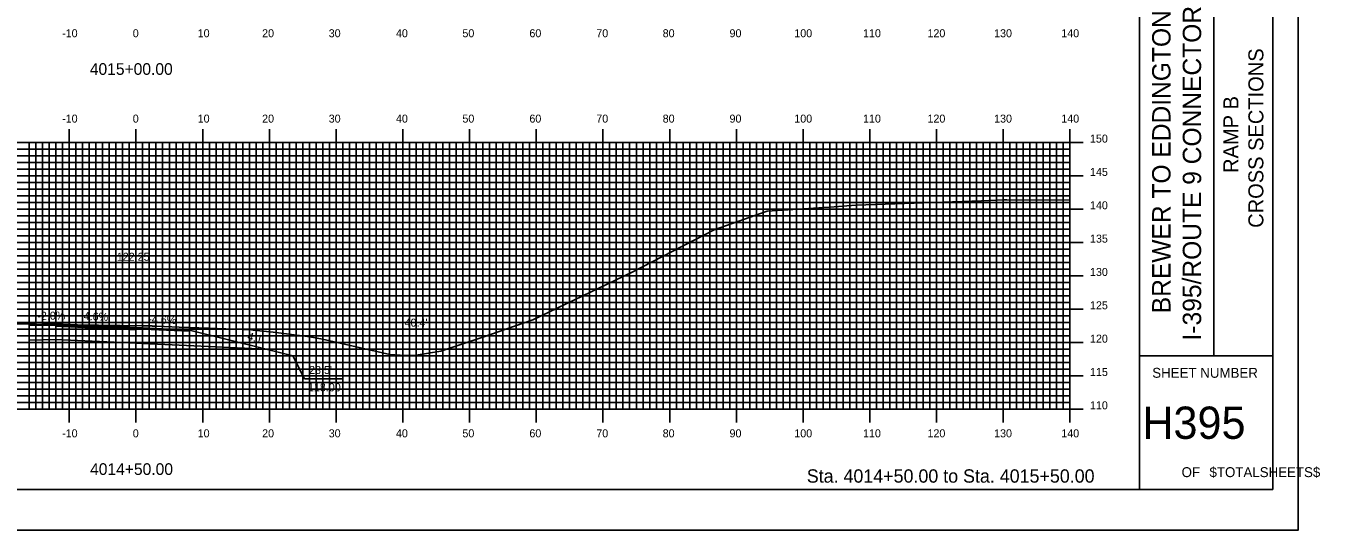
# Model space of a CAD drawing. Extents: x 853721 to 854064, y 364661 to 364881.
# Drawn here: x 853870.3 to 854064.3, y 364661.3 to 364736.9 of the extents above; entities that cross this region are included whole.
import ezdxf

# ---------------------------------------------------------------- set-up
doc = ezdxf.new("R2010")
doc.units = 0
for name, color, linetype in [('ANNOTATION', 7, 'Continuous'), ('BORDER', 7, 'Continuous'), ('D_Roadway_Centerline_Text', 7, 'Continuous'), ('D_Roadway_Edge_Shoulder', 7, 'Continuous'), ('D_Roadway_Edge_TW', 7, 'Continuous'), ('D_Roadway_Pavement', 7, 'Continuous'), ('D_Roadway_SubGrade', 7, 'Continuous'), ('D_Text_Standard', 7, 'Continuous'), ('H_V ANNOTATION', 7, 'Continuous'), ('M_Roadway_Centerline', 7, 'Continuous'), ('MAJOR', 7, 'Continuous'), ('MINOR', 7, 'Continuous'), ('PLOT BOUNDARY', 7, 'Continuous'), ('S_Roadway_Centerline', 7, 'Continuous')]:
    doc.layers.add(name, color=color, linetype=linetype)

msp = doc.modelspace()

# ---------------------------------------------------------------- linework, layer by layer
at = {"layer": 'ANNOTATION'}
for points in [[(853906.3, 364688.38), (853910.3, 364687.38), (853927.16, 364687.44)], [(853917.76, 364683.95), (853912.07, 364683.95), (853910.3, 364687.38)]]:
    msp.add_lwpolyline(points, dxfattribs=at)
at = {"layer": 'BORDER'}
for p, q in [((854037.21, 364667.37), (854037.21, 364877.37)), ((854048.39, 364687.38), (854048.39, 364757.38)), ((854037.21, 364687.38), (854057.21, 364687.38))]:
    msp.add_line(p, q, dxfattribs=at)
msp.add_lwpolyline([(853737.21, 364667.37), (854057.21, 364667.37), (854057.21, 364877.37), (853737.21, 364877.37)], close=True, dxfattribs=at)
at = {"layer": 'D_Roadway_Edge_Shoulder'}
for points in [[(853874.81, 364692.17), (853870.81, 364692.09), (853870.81, 364691.92), (853874.81, 364691.99)], [(853886.81, 364691.62), (853894.81, 364691.25), (853894.81, 364691.08), (853886.81, 364691.44)]]:
    msp.add_lwpolyline(points, close=True, dxfattribs=at)
at = {"layer": 'D_Roadway_Edge_TW'}
msp.add_lwpolyline([(853874.81, 364692.17), (853886.81, 364691.62), (853886.81, 364691.44), (853874.81, 364691.99)], close=True, dxfattribs=at)
at = {"layer": 'D_Roadway_Pavement'}
msp.add_lwpolyline([(853874.81, 364691.99), (853886.81, 364691.44), (853886.81, 364691.27), (853874.81, 364691.82)], close=True, dxfattribs=at)
for points in [[(853874.81, 364691.99), (853874.81, 364691.82)], [(853886.81, 364691.44), (853886.81, 364691.27)], [(853886.81, 364691.44), (853886.81, 364691.27)]]:
    msp.add_lwpolyline(points, dxfattribs=at)
at = {"layer": 'D_Roadway_SubGrade'}
msp.add_line((853870.81, 364699.37), (853870.81, 364689.74), dxfattribs=at)
for points in [[(853874.81, 364689.82), (853870.81, 364689.74), (853870.81, 364692.09), (853870.81, 364691.92), (853874.81, 364691.99), (853874.81, 364691.82)], [(853874.81, 364691.82), (853886.81, 364691.27), (853886.81, 364689.27), (853874.81, 364689.82)], [(853886.81, 364691.27), (853886.81, 364691.44), (853894.81, 364691.08), (853894.81, 364691.25), (853906.3, 364688.38), (853886.81, 364689.27)]]:
    msp.add_lwpolyline(points, close=True, dxfattribs=at)
at = {"layer": 'MAJOR'}
for p, q in [((853876.81, 364721.37), (853876.81, 364719.37)), ((853886.81, 364721.37), (853886.81, 364719.37)), ((853896.81, 364721.37), (853896.81, 364719.37)), ((853906.81, 364721.37), (853906.81, 364719.37)), ((853916.81, 364721.37), (853916.81, 364719.37)), ((853926.81, 364721.37), (853926.81, 364719.37)), ((853936.81, 364721.37), (853936.81, 364719.37)), ((853946.81, 364721.37), (853946.81, 364719.37)), ((853956.81, 364721.37), (853956.81, 364719.37)), ((853966.81, 364721.37), (853966.81, 364719.37)), ((853976.81, 364721.37), (853976.81, 364719.37)), ((853986.81, 364721.37), (853986.81, 364719.37)), ((853996.81, 364721.37), (853996.81, 364719.37)), ((854006.81, 364721.37), (854006.81, 364719.37)), ((854016.81, 364721.37), (854016.81, 364719.37)), ((854026.81, 364721.37), (854026.81, 364719.37)), ((853746.81, 364719.37), (854026.81, 364719.37)), ((853746.81, 364719.37), (854026.81, 364719.37)), ((853876.81, 364679.37), (853876.81, 364719.37)), ((853886.81, 364679.37), (853886.81, 364719.37)), ((853896.81, 364679.37), (853896.81, 364719.37)), ((853906.81, 364679.37), (853906.81, 364719.37)), ((853916.81, 364679.37), (853916.81, 364719.37)), ((853926.81, 364679.37), (853926.81, 364719.37)), ((853936.81, 364679.37), (853936.81, 364719.37)), ((853946.81, 364679.37), (853946.81, 364719.37)), ((853956.81, 364679.37), (853956.81, 364719.37)), ((853966.81, 364679.37), (853966.81, 364719.37)), ((853976.81, 364679.37), (853976.81, 364719.37)), ((853986.81, 364679.37), (853986.81, 364719.37)), ((853996.81, 364679.37), (853996.81, 364719.37)), ((854006.81, 364679.37), (854006.81, 364719.37)), ((854016.81, 364679.37), (854016.81, 364719.37)), ((854028.81, 364719.37), (854024.8, 364719.37)), ((854026.81, 364679.37), (854026.81, 364719.37)), ((854026.81, 364679.37), (854026.81, 364719.37)), ((853746.81, 364714.37), (854026.81, 364714.37)), ((854028.81, 364714.37), (854024.8, 364714.37)), ((853746.81, 364709.37), (854026.81, 364709.37)), ((854028.81, 364709.37), (854024.8, 364709.37)), ((853746.81, 364704.37), (854026.81, 364704.37)), ((854028.81, 364704.37), (854024.8, 364704.37)), ((853746.81, 364699.37), (854026.81, 364699.37)), ((854028.81, 364699.37), (854024.8, 364699.37)), ((853746.81, 364694.37), (854026.81, 364694.37)), ((854028.81, 364694.37), (854024.8, 364694.37)), ((853746.81, 364689.37), (854026.81, 364689.37)), ((854028.81, 364689.37), (854024.8, 364689.37)), ((853746.81, 364684.37), (854026.81, 364684.37)), ((854028.81, 364684.37), (854024.8, 364684.37)), ((853746.81, 364679.37), (854026.81, 364679.37)), ((853746.81, 364679.37), (854026.81, 364679.37)), ((853876.81, 364677.37), (853876.81, 364679.37)), ((853886.81, 364677.37), (853886.81, 364679.37)), ((853896.81, 364677.37), (853896.81, 364679.37)), ((853906.81, 364677.37), (853906.81, 364679.37)), ((853916.81, 364677.37), (853916.81, 364679.37)), ((853926.81, 364677.37), (853926.81, 364679.37)), ((853936.81, 364677.37), (853936.81, 364679.37)), ((853946.81, 364677.37), (853946.81, 364679.37)), ((853956.81, 364677.37), (853956.81, 364679.37)), ((853966.81, 364677.37), (853966.81, 364679.37)), ((853976.81, 364677.37), (853976.81, 364679.37)), ((853986.81, 364677.37), (853986.81, 364679.37)), ((853996.81, 364677.37), (853996.81, 364679.37)), ((854006.81, 364677.37), (854006.81, 364679.37)), ((854016.81, 364677.37), (854016.81, 364679.37)), ((854028.81, 364679.37), (854024.8, 364679.37)), ((854026.81, 364677.37), (854026.81, 364679.37))]:
    msp.add_line(p, q, dxfattribs=at)
at = {"layer": 'MINOR'}
for p, q in [((853870.81, 364679.37), (853870.81, 364719.37)), ((853871.81, 364679.37), (853871.81, 364719.37)), ((853872.81, 364679.37), (853872.81, 364719.37)), ((853873.81, 364679.37), (853873.81, 364719.37)), ((853874.81, 364679.37), (853874.81, 364719.37)), ((853875.81, 364679.37), (853875.81, 364719.37)), ((853877.81, 364679.37), (853877.81, 364719.37)), ((853878.81, 364679.37), (853878.81, 364719.37)), ((853879.81, 364679.37), (853879.81, 364719.37)), ((853880.81, 364679.37), (853880.81, 364719.37)), ((853881.81, 364679.37), (853881.81, 364719.37)), ((853882.81, 364679.37), (853882.81, 364719.37)), ((853883.81, 364679.37), (853883.81, 364719.37)), ((853884.81, 364679.37), (853884.81, 364719.37)), ((853885.81, 364679.37), (853885.81, 364719.37)), ((853887.81, 364679.37), (853887.81, 364719.37)), ((853888.81, 364679.37), (853888.81, 364719.37)), ((853889.81, 364679.37), (853889.81, 364719.37)), ((853890.81, 364679.37), (853890.81, 364719.37)), ((853891.81, 364679.37), (853891.81, 364719.37)), ((853892.81, 364679.37), (853892.81, 364719.37)), ((853893.81, 364679.37), (853893.81, 364719.37)), ((853894.81, 364679.37), (853894.81, 364719.37)), ((853895.81, 364679.37), (853895.81, 364719.37)), ((853897.81, 364679.37), (853897.81, 364719.37)), ((853898.81, 364679.37), (853898.81, 364719.37)), ((853899.81, 364679.37), (853899.81, 364719.37)), ((853900.81, 364679.37), (853900.81, 364719.37)), ((853901.81, 364679.37), (853901.81, 364719.37)), ((853902.81, 364679.37), (853902.81, 364719.37)), ((853903.81, 364679.37), (853903.81, 364719.37)), ((853904.81, 364679.37), (853904.81, 364719.37)), ((853905.81, 364679.37), (853905.81, 364719.37)), ((853907.81, 364679.37), (853907.81, 364719.37)), ((853908.81, 364679.37), (853908.81, 364719.37)), ((853909.81, 364679.37), (853909.81, 364719.37)), ((853910.81, 364679.37), (853910.81, 364719.37)), ((853911.81, 364679.37), (853911.81, 364719.37)), ((853912.81, 364679.37), (853912.81, 364719.37)), ((853913.81, 364679.37), (853913.81, 364719.37)), ((853914.81, 364679.37), (853914.81, 364719.37)), ((853915.81, 364679.37), (853915.81, 364719.37)), ((853917.81, 364679.37), (853917.81, 364719.37)), ((853918.81, 364679.37), (853918.81, 364719.37)), ((853919.81, 364679.37), (853919.81, 364719.37)), ((853920.81, 364679.37), (853920.81, 364719.37)), ((853921.81, 364679.37), (853921.81, 364719.37)), ((853922.81, 364679.37), (853922.81, 364719.37)), ((853923.81, 364679.37), (853923.81, 364719.37)), ((853924.81, 364679.37), (853924.81, 364719.37)), ((853925.81, 364679.37), (853925.81, 364719.37)), ((853927.81, 364679.37), (853927.81, 364719.37)), ((853928.81, 364679.37), (853928.81, 364719.37)), ((853929.81, 364679.37), (853929.81, 364719.37)), ((853930.81, 364679.37), (853930.81, 364719.37)), ((853931.81, 364679.37), (853931.81, 364719.37)), ((853932.81, 364679.37), (853932.81, 364719.37)), ((853933.81, 364679.37), (853933.81, 364719.37)), ((853934.81, 364679.37), (853934.81, 364719.37)), ((853935.81, 364679.37), (853935.81, 364719.37)), ((853937.81, 364679.37), (853937.81, 364719.37)), ((853938.81, 364679.37), (853938.81, 364719.37)), ((853939.81, 364679.37), (853939.81, 364719.37)), ((853940.81, 364679.37), (853940.81, 364719.37)), ((853941.81, 364679.37), (853941.81, 364719.37)), ((853942.81, 364679.37), (853942.81, 364719.37)), ((853943.81, 364679.37), (853943.81, 364719.37)), ((853944.81, 364679.37), (853944.81, 364719.37)), ((853945.81, 364679.37), (853945.81, 364719.37)), ((853947.81, 364679.37), (853947.81, 364719.37)), ((853948.81, 364679.37), (853948.81, 364719.37)), ((853949.81, 364679.37), (853949.81, 364719.37)), ((853950.81, 364679.37), (853950.81, 364719.37)), ((853951.81, 364679.37), (853951.81, 364719.37)), ((853952.81, 364679.37), (853952.81, 364719.37)), ((853953.81, 364679.37), (853953.81, 364719.37)), ((853954.81, 364679.37), (853954.81, 364719.37)), ((853955.81, 364679.37), (853955.81, 364719.37)), ((853957.81, 364679.37), (853957.81, 364719.37)), ((853958.81, 364679.37), (853958.81, 364719.37)), ((853959.81, 364679.37), (853959.81, 364719.37)), ((853960.81, 364679.37), (853960.81, 364719.37)), ((853961.81, 364679.37), (853961.81, 364719.37)), ((853962.81, 364679.37), (853962.81, 364719.37)), ((853963.81, 364679.37), (853963.81, 364719.37)), ((853964.81, 364679.37), (853964.81, 364719.37)), ((853965.81, 364679.37), (853965.81, 364719.37)), ((853967.81, 364679.37), (853967.81, 364719.37)), ((853968.81, 364679.37), (853968.81, 364719.37)), ((853969.81, 364679.37), (853969.81, 364719.37)), ((853970.81, 364679.37), (853970.81, 364719.37)), ((853971.81, 364679.37), (853971.81, 364719.37)), ((853972.81, 364679.37), (853972.81, 364719.37)), ((853973.81, 364679.37), (853973.81, 364719.37)), ((853974.81, 364679.37), (853974.81, 364719.37)), ((853975.81, 364679.37), (853975.81, 364719.37)), ((853977.81, 364679.37), (853977.81, 364719.37)), ((853978.81, 364679.37), (853978.81, 364719.37)), ((853979.81, 364679.37), (853979.81, 364719.37)), ((853980.81, 364679.37), (853980.81, 364719.37)), ((853981.81, 364679.37), (853981.81, 364719.37)), ((853982.81, 364679.37), (853982.81, 364719.37)), ((853983.81, 364679.37), (853983.81, 364719.37)), ((853984.81, 364679.37), (853984.81, 364719.37)), ((853985.81, 364679.37), (853985.81, 364719.37)), ((853987.81, 364679.37), (853987.81, 364719.37)), ((853988.81, 364679.37), (853988.81, 364719.37)), ((853989.81, 364679.37), (853989.81, 364719.37)), ((853990.81, 364679.37), (853990.81, 364719.37)), ((853991.81, 364679.37), (853991.81, 364719.37)), ((853992.81, 364679.37), (853992.81, 364719.37)), ((853993.81, 364679.37), (853993.81, 364719.37)), ((853994.81, 364679.37), (853994.81, 364719.37)), ((853995.81, 364679.37), (853995.81, 364719.37)), ((853997.81, 364679.37), (853997.81, 364719.37)), ((853998.81, 364679.37), (853998.81, 364719.37)), ((853999.81, 364679.37), (853999.81, 364719.37)), ((854000.81, 364679.37), (854000.81, 364719.37)), ((854001.81, 364679.37), (854001.81, 364719.37)), ((854002.81, 364679.37), (854002.81, 364719.37)), ((854003.81, 364679.37), (854003.81, 364719.37)), ((854004.81, 364679.37), (854004.81, 364719.37)), ((854005.81, 364679.37), (854005.81, 364719.37)), ((854007.81, 364679.37), (854007.81, 364719.37)), ((854008.81, 364679.37), (854008.81, 364719.37)), ((854009.81, 364679.37), (854009.81, 364719.37)), ((854010.81, 364679.37), (854010.81, 364719.37)), ((854011.81, 364679.37), (854011.81, 364719.37)), ((854012.81, 364679.37), (854012.81, 364719.37)), ((854013.81, 364679.37), (854013.81, 364719.37)), ((854014.81, 364679.37), (854014.81, 364719.37)), ((854015.81, 364679.37), (854015.81, 364719.37)), ((854017.81, 364679.37), (854017.81, 364719.37)), ((854018.81, 364679.37), (854018.81, 364719.37)), ((854019.81, 364679.37), (854019.81, 364719.37)), ((854020.81, 364679.37), (854020.81, 364719.37)), ((854021.81, 364679.37), (854021.81, 364719.37)), ((854022.81, 364679.37), (854022.81, 364719.37)), ((854023.81, 364679.37), (854023.81, 364719.37)), ((854024.81, 364679.37), (854024.81, 364719.37)), ((854025.81, 364679.37), (854025.81, 364719.37)), ((853746.81, 364718.37), (854026.81, 364718.37)), ((853746.81, 364717.37), (854026.81, 364717.37)), ((854026.81, 364718.37), (854024.8, 364718.37)), ((854026.81, 364717.37), (854024.8, 364717.37)), ((853746.81, 364716.37), (854026.81, 364716.37)), ((853746.81, 364715.37), (854026.81, 364715.37)), ((854026.81, 364716.37), (854024.8, 364716.37)), ((854026.81, 364715.37), (854024.8, 364715.37)), ((853746.81, 364713.37), (854026.81, 364713.37)), ((854026.81, 364713.37), (854024.8, 364713.37)), ((853746.81, 364712.37), (854026.81, 364712.37)), ((853746.81, 364711.37), (854026.81, 364711.37)), ((854026.81, 364712.37), (854024.8, 364712.37)), ((854026.81, 364711.37), (854024.8, 364711.37)), ((853746.81, 364710.37), (854026.81, 364710.37)), ((854026.81, 364710.37), (854024.8, 364710.37)), ((853746.81, 364708.37), (854026.81, 364708.37)), ((853746.81, 364707.37), (854026.81, 364707.37)), ((854026.81, 364708.37), (854024.8, 364708.37)), ((854026.81, 364707.37), (854024.8, 364707.37)), ((853746.81, 364706.37), (854026.81, 364706.37)), ((853746.81, 364705.37), (854026.81, 364705.37)), ((854026.81, 364706.37), (854024.8, 364706.37)), ((854026.81, 364705.37), (854024.8, 364705.37)), ((853746.81, 364703.37), (854026.81, 364703.37)), ((854026.81, 364703.37), (854024.8, 364703.37)), ((853746.81, 364702.37), (854026.81, 364702.37)), ((853746.81, 364701.37), (854026.81, 364701.37)), ((854026.81, 364702.37), (854024.8, 364702.37)), ((854026.81, 364701.37), (854024.8, 364701.37)), ((853746.81, 364700.37), (854026.81, 364700.37)), ((854026.81, 364700.37), (854024.8, 364700.37)), ((853746.81, 364698.37), (854026.81, 364698.37)), ((853746.81, 364697.37), (854026.81, 364697.37)), ((854026.81, 364698.37), (854024.8, 364698.37)), ((854026.81, 364697.37), (854024.8, 364697.37)), ((853746.81, 364696.37), (854026.81, 364696.37)), ((853746.81, 364695.37), (854026.81, 364695.37)), ((854026.81, 364696.37), (854024.8, 364696.37)), ((854026.81, 364695.37), (854024.8, 364695.37)), ((853746.81, 364693.37), (854026.81, 364693.37)), ((854026.81, 364693.37), (854024.8, 364693.37)), ((853746.81, 364692.37), (854026.81, 364692.37)), ((853746.81, 364691.37), (854026.81, 364691.37)), ((854026.81, 364692.37), (854024.8, 364692.37)), ((854026.81, 364691.37), (854024.8, 364691.37)), ((853746.81, 364690.37), (854026.81, 364690.37)), ((854026.81, 364690.37), (854024.8, 364690.37)), ((853746.81, 364688.37), (854026.81, 364688.37)), ((854026.81, 364688.37), (854024.8, 364688.37)), ((853746.81, 364687.37), (854026.81, 364687.37)), ((853746.81, 364686.37), (854026.81, 364686.37)), ((854026.81, 364687.37), (854024.8, 364687.37)), ((854026.81, 364686.37), (854024.8, 364686.37)), ((853746.81, 364685.37), (854026.81, 364685.37)), ((854026.81, 364685.37), (854024.8, 364685.37)), ((853746.81, 364683.37), (854026.81, 364683.37)), ((853746.81, 364682.37), (854026.81, 364682.37)), ((854026.81, 364683.37), (854024.8, 364683.37)), ((854026.81, 364682.37), (854024.8, 364682.37)), ((853746.81, 364681.37), (854026.81, 364681.37)), ((853746.81, 364680.37), (854026.81, 364680.37)), ((854026.81, 364681.37), (854024.8, 364681.37)), ((854026.81, 364680.37), (854024.8, 364680.37))]:
    msp.add_line(p, q, dxfattribs=at)
at = {"layer": 'PLOT BOUNDARY'}
msp.add_lwpolyline([(853721.02, 364661.25), (854061.02, 364661.25), (854061.02, 364881.25), (853721.02, 364881.25)], close=True, dxfattribs=at)
at = {"layer": 'S_Roadway_Centerline'}
msp.add_lwpolyline([(853868.81, 364692.17), (853877.39, 364692.06), (853881.17, 364691.97), (853887.73, 364691.88), (853889.26, 364691.87), (853889.26, 364691.86), (853889.4, 364691.86), (853889.94, 364691.84), (853893.27, 364691.67), (853897.69, 364691.52), (853902.91, 364691.35), (853904.11, 364691.3), (853904.19, 364691.27), (853904.37, 364691.25), (853907.39, 364690.92), (853912.53, 364690.3), (853913.41, 364690.16), (853914.75, 364689.9), (853924.88, 364687.59), (853927.16, 364687.44), (853928.8, 364687.48), (853932.49, 364688.11), (853938.65, 364690.13), (853946.29, 364692.77), (853961.17, 364699.96), (853973.47, 364706.27), (853981.42, 364709.08), (853991.47, 364709.76), (853993.34, 364709.89), (853994.75, 364709.99), (854013.55, 364710.66), (854016.87, 364710.78), (854017.36, 364710.79), (854026.81, 364710.75)], dxfattribs=at)

# ---------------------------------------------------------------- texts
at = {"layer": 'ANNOTATION'}
for s, rotation, p in [('-2.0%', 1.1458, (853872.04, 364692.77)), ('4.6%', 357.3663, (853878.95, 364692.78)), ('-4.6%', 357.3663, (853888.63, 364692.33)), ('4:1', 345.9638, (853903.43, 364689.81))]:
    msp.add_text(s, height=1.2, rotation=rotation, dxfattribs=at).set_placement(p)
for s, p in [("23.5' ", (853912.76, 364684.67)), ('118.00', (853912.59, 364682.07))]:
    msp.add_text(s, height=1.2, dxfattribs=at).set_placement(p)
at = {"layer": 'BORDER'}
for s, height, p in [('BREWER TO EDDINGTON', 2.7557, (854041.88, 364693.78)), ('I-395/ROUTE 9 CONNECTOR', 2.7557, (854046.47, 364689.7)), ('CROSS SECTIONS', 2.25, (854055.8, 364706.59)), ('RAMP B', 2.25, (854052.05, 364714.82))]:
    msp.add_text(s, height=height, rotation=90, dxfattribs=at).set_placement(p)
for s, height, p in [('SHEET NUMBER', 1.4905, (854039.14, 364684.1)), ('H395', 4.839, (854037.65, 364674.94)), ('OF', 1.491, (854043.54, 364669.2)), ('$TOTALSHEETS$', 1.4905, (854047.72, 364669.2))]:
    msp.add_text(s, height=height, dxfattribs=at).set_placement(p)
at = {"layer": 'D_Roadway_Centerline_Text'}
msp.add_text('122.25', height=1.2, dxfattribs=at).set_placement((853883.94, 364701.65))
at = {"layer": 'D_Text_Standard'}
msp.add_text("40.4'", height=1.2, dxfattribs=at).set_placement((853927.08, 364691.77))
at = {"layer": 'H_V ANNOTATION'}
for s, height, p in [('-10', 1.2, (853875.74, 364735.17)), ('0', 1.2, (853886.33, 364735.17)), ('10', 1.2, (853896.06, 364735.17)), ('20', 1.2, (853905.72, 364735.17)), ('30', 1.2, (853915.7, 364735.17)), ('40', 1.2, (853925.78, 364735.17)), ('50', 1.2, (853935.74, 364735.17)), ('60', 1.2, (853945.78, 364735.17)), ('70', 1.2, (853955.81, 364735.17)), ('80', 1.2, (853965.76, 364735.17)), ('90', 1.2, (853975.78, 364735.17)), ('100', 1.2, (853985.49, 364735.17)), ('110', 1.2, (853995.79, 364735.17)), ('120', 1.2, (854005.45, 364735.17)), ('130', 1.2, (854015.44, 364735.17)), ('140', 1.2, (854025.51, 364735.17)), ('4015+00.00', 1.75, (853879.89, 364729.53)), ('-10', 1.2, (853875.74, 364722.37)), ('0', 1.2, (853886.33, 364722.37)), ('10', 1.2, (853896.06, 364722.37)), ('20', 1.2, (853905.72, 364722.37)), ('30', 1.2, (853915.7, 364722.37)), ('40', 1.2, (853925.78, 364722.37)), ('50', 1.2, (853935.74, 364722.37)), ('60', 1.2, (853945.78, 364722.37)), ('70', 1.2, (853955.81, 364722.37)), ('80', 1.2, (853965.76, 364722.37)), ('90', 1.2, (853975.78, 364722.37)), ('100', 1.2, (853985.49, 364722.37)), ('110', 1.2, (853995.79, 364722.37)), ('120', 1.2, (854005.45, 364722.37)), ('130', 1.2, (854015.44, 364722.37)), ('140', 1.2, (854025.51, 364722.37)), ('150', 1.2, (854029.81, 364719.37)), ('145', 1.2, (854029.81, 364714.37)), ('140', 1.2, (854029.81, 364709.37)), ('135', 1.2, (854029.81, 364704.37)), ('130', 1.2, (854029.81, 364699.37)), ('125', 1.2, (854029.81, 364694.37)), ('120', 1.2, (854029.81, 364689.37)), ('115', 1.2, (854029.81, 364684.37)), ('110', 1.2, (854029.81, 364679.37)), ('-10', 1.2, (853875.74, 364675.17)), ('0', 1.2, (853886.33, 364675.17)), ('10', 1.2, (853896.06, 364675.17)), ('20', 1.2, (853905.72, 364675.17)), ('30', 1.2, (853915.7, 364675.17)), ('40', 1.2, (853925.78, 364675.17)), ('50', 1.2, (853935.74, 364675.17)), ('60', 1.2, (853945.78, 364675.17)), ('70', 1.2, (853955.81, 364675.17)), ('80', 1.2, (853965.76, 364675.17)), ('90', 1.2, (853975.78, 364675.17)), ('100', 1.2, (853985.49, 364675.17)), ('110', 1.2, (853995.79, 364675.17)), ('120', 1.2, (854005.45, 364675.17)), ('130', 1.2, (854015.44, 364675.17)), ('140', 1.2, (854025.51, 364675.17)), ('4014+50.00', 1.75, (853879.93, 364669.53)), ('Sta. 4014+50.00 to Sta. 4015+50.00', 2.0004, (853987.36, 364668.37))]:
    msp.add_text(s, height=height, dxfattribs=at).set_placement(p)
at = {"layer": 'M_Roadway_Centerline'}
for s, p in [('C', (853889.25, 364691.87)), ('L', (853889.26, 364691.86))]:
    msp.add_text(s, height=0.0146, dxfattribs=at).set_placement(p)

doc.saveas('drawing.dxf')
